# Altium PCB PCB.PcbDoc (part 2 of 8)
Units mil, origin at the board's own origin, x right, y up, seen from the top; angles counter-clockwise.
Board outline 11229.24 x 7764.43 mil, 14 copper layers (Top Layer, GND1, Signal 1, GND2, Signal 2, GND3, Singal 3, Power 1, GND4, Power 2, GND5, Power 3, GND6, Bottom Layer), stack 91.892 mil thick; 877 components, 305 nets, 2660 pads, 2851 vias.
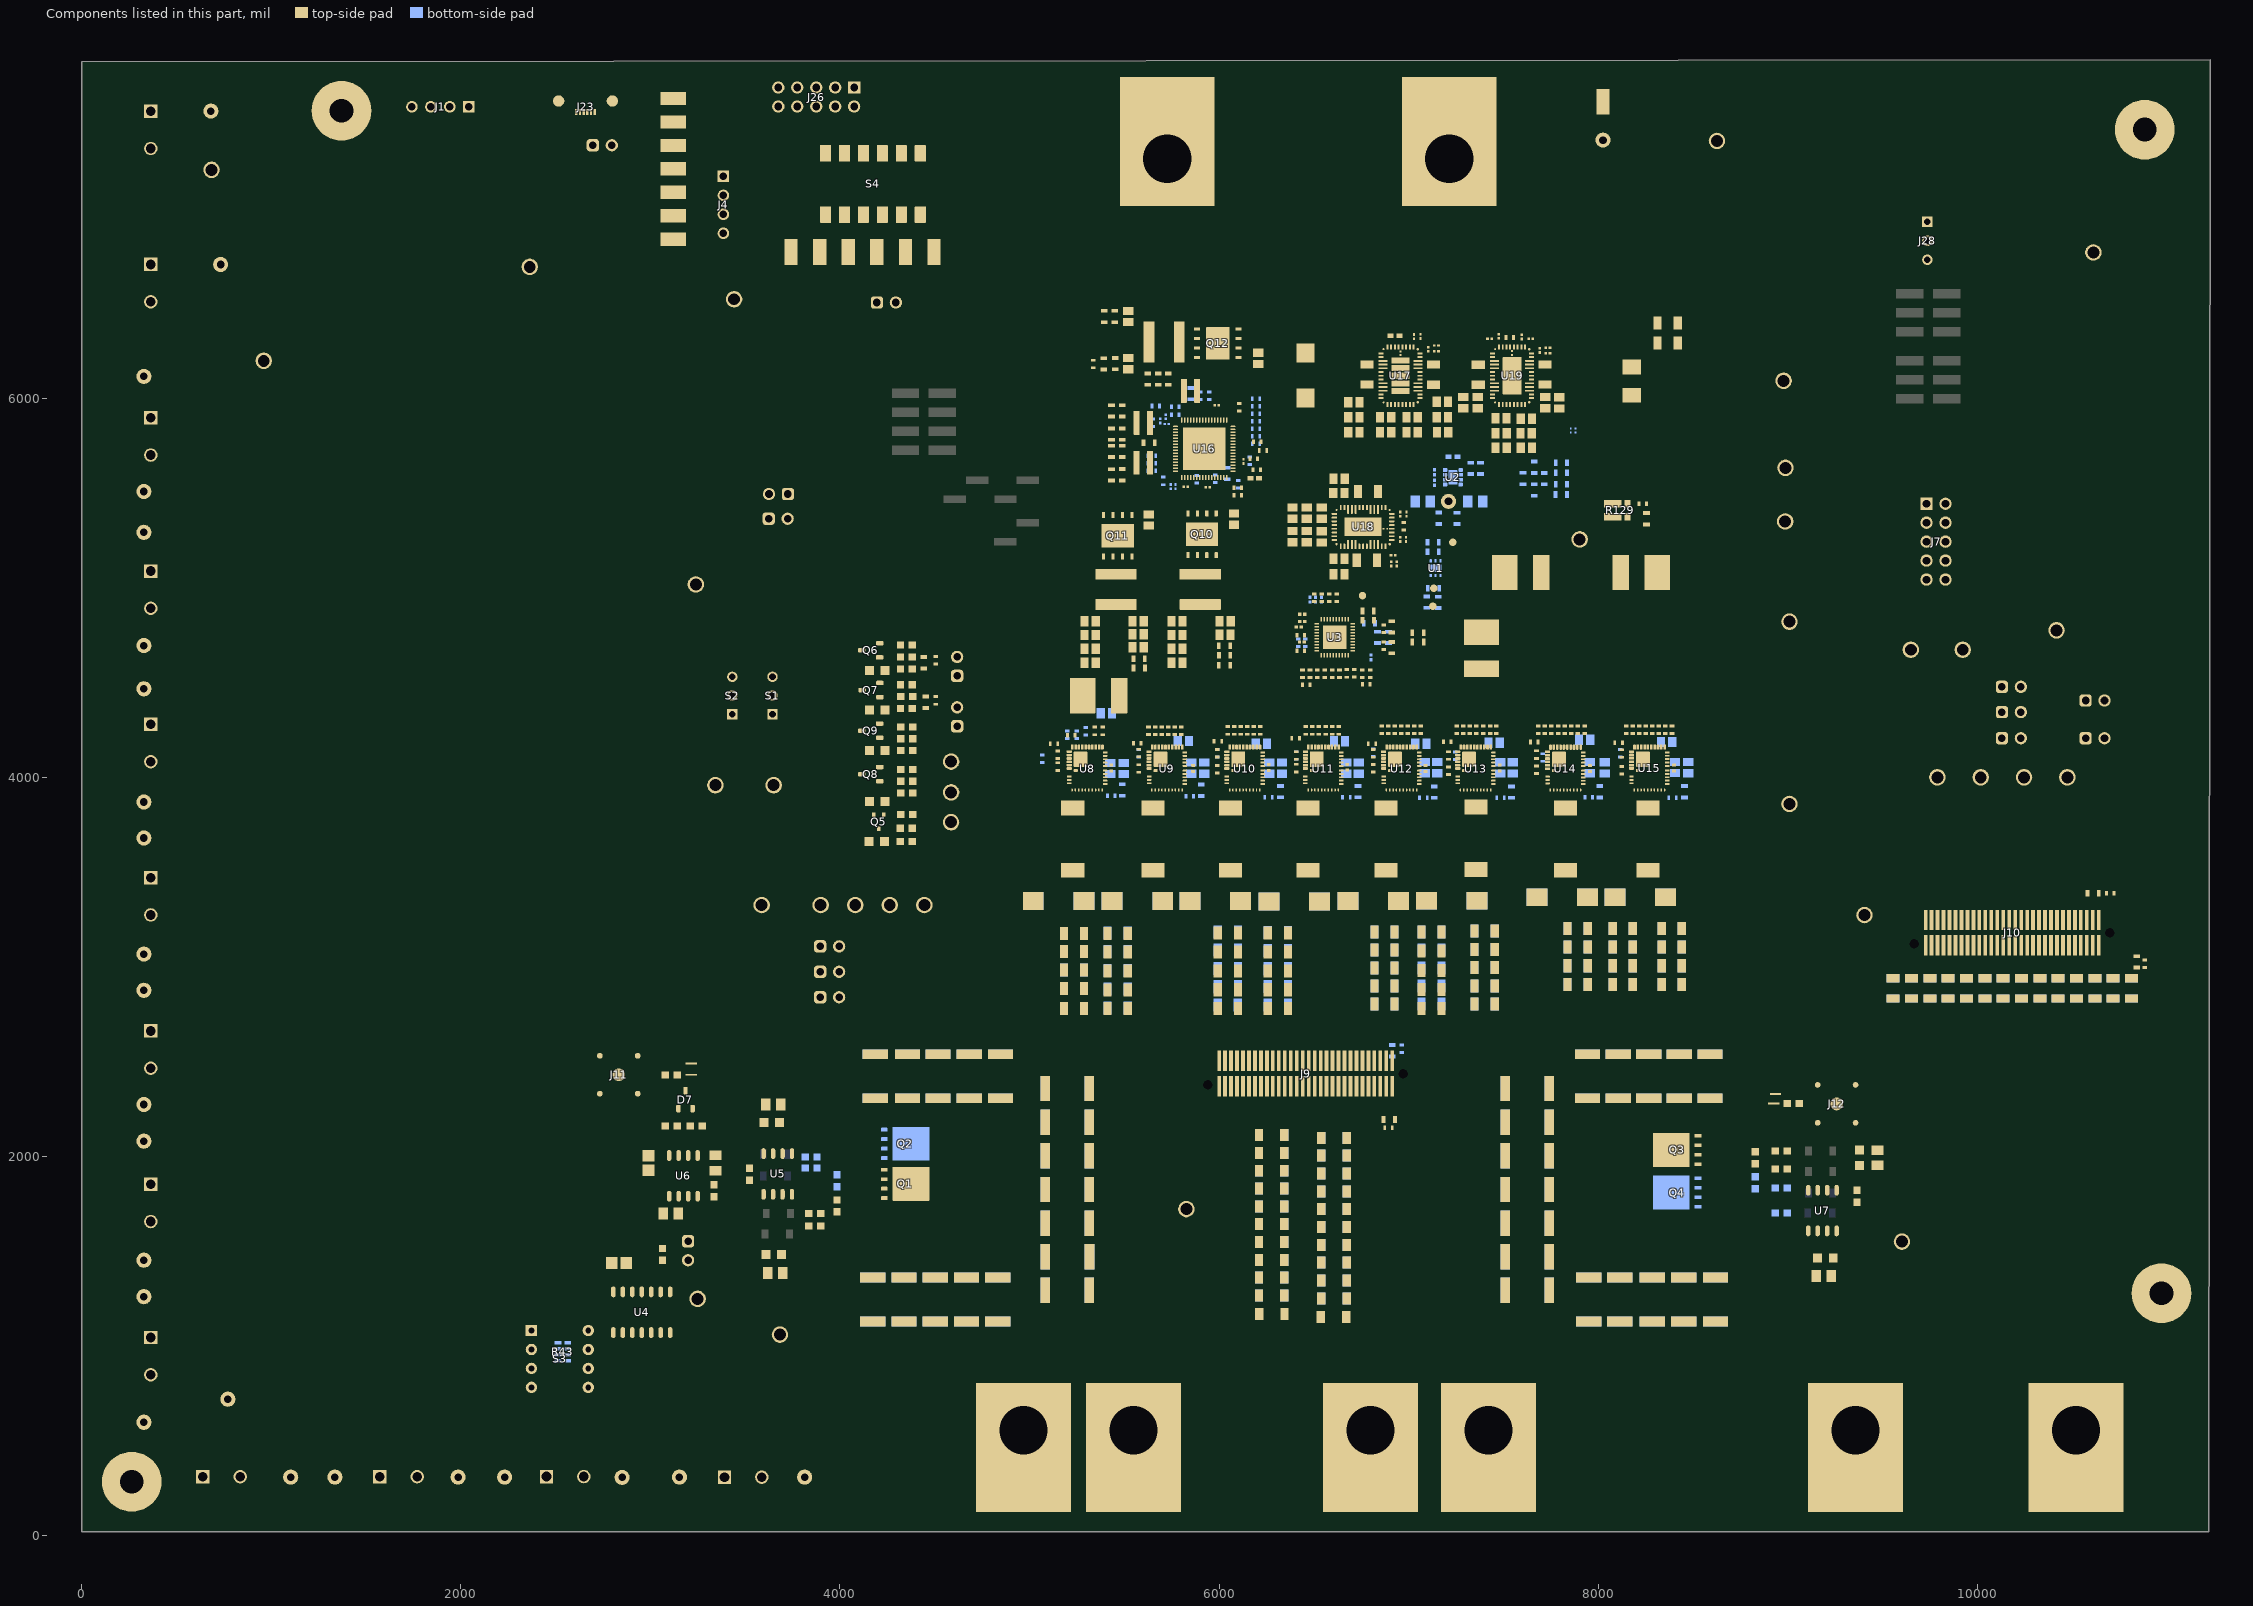
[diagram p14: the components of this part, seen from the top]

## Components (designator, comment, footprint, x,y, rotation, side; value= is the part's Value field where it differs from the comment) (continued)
J40 "TSW-102-07-G-S" TSW-102-07-G-S 10180,4477 r0 top
J41 "TSW-102-07-G-S" TSW-102-07-G-S 10180,4344 r0 top
J42 "TSW-102-07-G-S" TSW-102-07-G-S 10180,4205.9 r0 top
J43 "TSW-102-07-G-S" TSW-102-07-G-S 10621.2,4405.1 r0 top
J44 "TSW-102-07-G-S" TSW-102-07-G-S 10621.2,4205.9 r0 top
L1 "PA4059.550HLT" FP-PA4059.550HLT_SMT_IND_5MM5_5MM7-MFG 8177.1,6090.13 r270 top value=55nH
L2 "SLR1050A-151KEB" SLR1050 5228.42,3673.95 r270 top value=150nH
L3 "SLR1050A-151KEB" SLR1050 5651.54,3673.95 r270 top value=150nH
L4 "SLR1050A-151KEB" SLR1050 6061.26,3673.95 r270 top value=150nH
L5 "SLR1050A-151KEB" SLR1050 6470.18,3673.95 r270 top value=150nH
L6 "SLR1050A-151KEB" SLR1050 6880.87,3673.95 r270 top value=150nH
L7 "SLR1050A-151KEB" SLR1050 7355.5,3678.4 r270 top value=150nH
L8 "SLR1050A-151KEB" SLR1050 7827.39,3673.95 r270 top value=150nH
L9 "SLR1050A-151KEB" SLR1050 8262.09,3673.95 r270 top value=150nH
L10 "XEL6030-471MEB" XEL6030_320 5900.8,4991.17 r270 top value=470nH
L11 "XEL6030-471MEB" XEL6030_320 5456.32,4991.17 r270 top value=470nH
L12 "XEL6030-471MEB" XEL6030_320 5710.13,6296.76 r180 top value=470nH
L13 "XEL3530-501MEC" FP-XEL3530-501MEC_SMT_IND_3MM2_3MM5-MFG 5849.36,6038.36 r180 top
L14 "XEL3530-501MEC" FP-XEL3530-501MEC_SMT_IND_3MM2_3MM5-MFG 5600.97,5659.2 r180 top
L15 "XEL3530-501MEC" FP-XEL3530-501MEC_SMT_IND_3MM2_3MM5-MFG 5600.97,5869.4 r180 top
Logo1 "CE Mark" CE_Mark_5mm 1678.6,4168.8 r0 top
Logo2 "Texas Instruments" TI_Stacked_Overlay_Small 1882.7,4588.7 r0 top
Logo3 "FCC disclaimer" FCC_disclaimer 2144.7,4396.1 r0 top
Logo4 "WEEE logo" WEEE_Minimum 2036.82,4195.72 r0 top
NT1 "Net-Tie" Net-Tie_10mil 7855.14,5829.36 r270 bottom net-tie
NT2 "Net-Tie" Net-Tie_10mil 7881.1,5829.36 r270 bottom net-tie
NT3 "Net-Tie" Net-Tie_10milWide_30milLong 3215.02,2430.69 r180 top net-tie
NT4 "Net-Tie" Net-Tie_10milWide_30milLong 8925.61,2278.57 r0 top net-tie
NT5 "Net-Tie" Net-Tie_10milWide_30milLong 3215.02,2489.38 r180 top net-tie
NT6 "Net-Tie" Net-Tie_10milWide_30milLong 8935.8,2329.7 r0 top net-tie
NT7 "Net-Tie" Net-Tie6milsWide_20milsLong#1 6822.7,5859.51 r0 top net-tie
NT8 "Net-Tie" Net-Tie6milsWide_20milsLong#1 6053.81,5058.82 r270 top net-tie
NT9 "Net-Tie" Net-Tie6milsWide_20milsLong#2 5493.3,5367 r270 top net-tie
NT10 "Net-Tie" Net-Tie6milsWide_20milsLong#1 5295.9,4957.3 r270 top net-tie
NT11 "Net-Tie" Net-Tie6milsWide_20milsLong#1 6103.7,6131.5 r90 top net-tie
NT12 "Net-Tie" Net-Tie6milsWide_20milsLong#1 5717.57,6493.5 r180 top net-tie
NT13 "Net-Tie" Net-Tie6milsWide_20milsLong#1 5819.6,5994.97 r90 top net-tie
NT14 "Net-Tie" Net-Tie6milsWide_20milsLong#1 5562.4,5732.45 r180 top net-tie
NT15 "Net-Tie" Net-Tie6milsWide_20milsLong#1 5562.4,5792.5 r180 top net-tie
NT16 "Net-Tie" Net-Tie_10mil 6957.21,6237.02 r90 top net-tie
NT17 "Net-Tie" Net-Tie_10mil 6877.3,5310.89 r180 top net-tie
NT18 "Net-Tie" Net-Tie_10mil 7545.53,6238.47 r270 top net-tie
NT19 "Net-Tie" Net-Tie6milsWide_20milsLong#1 5937.93,5367 r270 top net-tie
Q1 "CSD17303Q5" DQH0008A#1 4344.24,1854.75 r0 top value=30V
Q2 "CSD17303Q5" DQH0008A#2 4344.24,2066.03 r0 bottom value=30V
Q3 "CSD17303Q5" DQH0008A#1 8416.65,2033.71 r180 top value=30V
Q4 "CSD17303Q5" DQH0008A#2 8416.65,1809.31 r180 bottom value=30V
Q5 "BSS223PWH6327" SOT-323 4204.38,3765.6 r270 top value=-20V
Q6 "BSS123" SOT-23 4162.63,4669.5 r180 top value=100V
Q7 "BSS123" SOT-23 4163.8,4460 r180 top value=100V
Q8 "BSS123" SOT-23 4162.67,4016.53 r180 top value=100V
Q9 "BSS123" SOT-23 4162.63,4245.95 r180 top value=100V
Q10 "CSD86360Q5D" DQY0008A 5910.18,5281.81 r270 top value=25V
Q11 "CSD86360Q5D" DQY0008A 5465.35,5274.01 r270 top value=25V
Q12 "CSD86360Q5D" DQY0008A 5993.26,6289.17 r180 top value=25V
R1 "RC0603FR-071RL" 0603S 7255.51,5366 r270 bottom value=1.00
R2 "RC0603FR-071RL" 0603S 7158.59,5366.17 r270 bottom value=1.00
R3 "RC0201FR-07523KL" 0201 7136.95,5553.61 r270 bottom value=523k
R4 "CRCW06030000Z0EA" 0603S 7328.7,5629.22 r270 bottom value=0
R5 "RC0603FR-071RL" 0603S 7156.93,4922.57 r270 bottom value=1.00
R6 "CRCW0201100KFKED" 0201 7136.95,5608.54 r270 bottom value=100k
R7 "CRCW04020000Z0ED" 0402S 6440.11,4546.38 r90 top value=0
R8 "CRCW06030000Z0EA" 0603S 6913.4,2557.4 r270 bottom value=0
R9 "CRCW04020000Z0ED" 0402S 6479.67,4546.38 r90 top value=0
R10 "CRCW06030000Z0EA" 0603S 10611.24,3387.33 r180 top value=0
R11 "CRCW04020000Z0ED" 0402S 6798.43,4546.38 r90 top value=0
R12 "CRCW04020000Z0ED" 0402S 6754.52,4546.38 r90 top value=0
R13 "CRCW060320K0FKEA" 0603S 6893.65,4737.98 r270 bottom value=20.0k
R14 "CRCW06031M30FKEA" 0603S 6836.07,4737.9 r270 bottom value=1.30Meg
R15 "CRCW06030000Z0EA" 0603S 6897.7,2194.33 r0 top value=0
R16 "CRCW06030000Z0EA" 0603S 10840.47,3026.33 r90 top value=0
R17 "CRCW06030000Z0EA" 0603S 6786.32,4877.05 r0 top value=0
R18 "CRCW040259K0FKED" 0402S 6417.31,4709.51 r90 bottom value=59.0k
R19 "CRCW040220K0JNED" 0402S 6454.62,4709.59 r90 bottom value=20k
R20 "CRCW04020000Z0ED" 0402S 6431.59,4667.4 r0 top value=0
R21 "CRCW04020000Z0ED" 0402S 6431.3,4748.7 r0 top value=0
R22 "CRCW06031K00JNEA" 0603S 4453.15,4395.6 r270 top value=1.0k
R23 "CRCW06031K00JNEA" 0603S 4442.9,4603.9 r270 top value=1.0k
R24 "CRCW06030000Z0EA" 0603S 7805.91,5658.39 r180 bottom value=0
R25 "CRCW06030000Z0EA" 0603S 7049.59,4763.14 r0 top value=0
R26 "CRCW06030000Z0EA" 0603S 7805.91,5605.71 r180 bottom value=0
R27 "CRCW06030000Z0EA" 0603S 7049.59,4713.53 r0 top value=0
R28 "CRCW06030000Z0EA" 0603S 7714.7,5575.4 r90 bottom value=0
R29 "CRCW06030000Z0EA" 0603S 7805.91,5545.7 r180 bottom value=0
R30 "RC0201JR-7D10KL" 0201 6508.29,4937.78 r90 bottom value=10k
R31 "RC0201JR-7D10KL" 0201 6438.6,4822.31 r180 top value=10k
R32 "RC0201JR-7D10KL" 0201 6540.67,4937.78 r90 bottom value=10k
R33 "CRCW0603121KFKEA" 0603S 6911.63,4793.14 r270 top value=121k
R34 "RC0201JR-7D10KL" 0201 6419.75,4793.38 r180 top value=10k
R35 "RC0201JR-7D10KL" 0201 6437.5,4714.2 r180 top value=10k
R36 "RC0201JR-7D10KL" 0201 6801.08,4631.96 r270 bottom value=10k
R37 "CRCW0603121KFKEA" 0603S 6911.89,4684.2 r90 top value=121k
R38 "CRCW06030000Z0EA" 0603S 7805.4,5491.9 r180 bottom value=0
R39 "CSRN2512FKR200" 2512 4186.6,2422.84 r90 top value=0.2
R40 "CSRN2512FKR200" 2512 4356.56,2422.84 r90 top value=0.2
R41 "CSRN2512FKR200" 2512 4172.95,1245.3 r270 bottom value=0.2
R42 "CSRN2512FKR200" 2512 4337.81,1245.3 r270 bottom value=0.2
R43 "TC164-JR-0710KL" TC164 2538.5,969.1 r180 bottom value=10k
R44 "CSRN2512FKR200" 2512 5198.84,2003.01 r0 top value=0.2
R45 "CSRN2512FKR200" 2512 5198.84,2180.51 r0 top value=0.2
R46 "CSRN2512FKR200" 2512 5198.84,2358 r0 top value=0.2
R47 "CSRN2512FKR200" 2512 5198.84,1825.52 r0 top value=0.2
R48 "CSRN2512FKR200" 2512 5198.84,1648.03 r0 top value=0.2
R49 "CSRN2512FKR200" 2512 5199.93,1470.53 r0 top value=0.2
R50 "CSRN2512FKR200" 2512 5198.84,1293.04 r0 top value=0.2
R51 "CSRN2512FKR200" 2512 4172.95,1245.3 r270 top value=0.2
R52 "CSRN2512FKR200" 2512 4337.81,1245.3 r270 top value=0.2
R53 "CSRN2512FKR200" 2512 4502.68,1245.3 r270 top value=0.2
R54 "CSRN2512FKR200" 2512 4667.54,1245.3 r270 top value=0.2
R55 "CSRN2512FKR200" 2512 4832.4,1245.3 r270 top value=0.2
R56 "CSRN2512FKR200" 2512 4847.12,2422.84 r90 top value=0.2
R57 "CSRN2512FKR200" 2512 4682.36,2422.84 r90 top value=0.2
R58 "CSRN2512FKR200" 2512 4517.49,2422.84 r90 top value=0.2
R59 "CSRN2512FKR200" 2512 4502.68,1245.3 r270 bottom value=0.2
R60 "CSRN2512FKR200" 2512 4186.6,2422.84 r90 bottom value=0.2
R61 "CSRN2512FKR200" 2512 4356.56,2422.84 r90 bottom value=0.2
R62 "CSRN2512FKR200" 2512 4517.49,2422.84 r90 bottom value=0.2
R63 "CSRN2512FKR200" 2512 4682.36,2422.84 r90 bottom value=0.2
R64 "CSRN2512FKR200" 2512 4847.12,2422.84 r90 bottom value=0.2
R65 "CSRN2512FKR200" 2512 5198.84,2358 r0 bottom value=0.2
R66 "CSRN2512FKR200" 2512 5198.84,2180.51 r0 bottom value=0.2
R67 "CSRN2512FKR200" 2512 5198.84,2003.02 r0 bottom value=0.2
R68 "CSRN2512FKR200" 2512 5198.84,1825.52 r0 bottom value=0.2
R69 "CSRN2512FKR200" 2512 5198.84,1648.03 r0 bottom value=0.2
R70 "CSRN2512FKR200" 2512 5199.93,1470.53 r0 bottom value=0.2
R71 "CSRN2512FKR200" 2512 5198.84,1293.04 r0 bottom value=0.2
R72 "CSRN2512FKR200" 2512 4832.4,1245.3 r270 bottom value=0.2
R73 "CSRN2512FKR200" 2512 4667.54,1245.3 r270 bottom value=0.2
R74 "CRCW060375R0FKEA" 0603 3866.21,1633 r0 top value=75.0
R75 "CRCW060375R0FKEA" 0603 3847.51,1996 r0 bottom value=75.0
R76 "CRCW0805330RJNEA" 0805_HV 3659.52,1384.14 r180 top value=330
R77 "CRCW0603100RFKEA" 0603 3866.21,1699.1 r0 top value=100
R78 "CRCW0603100RFKEA" 0603 3847.51,1937.82 r0 bottom value=100
R79 "CRCW060310K0JNEA" 0603 3984.32,1738.47 r270 top value=10k
R80 "CRCW060310K0JNEA" 0603 3984.32,1871.89 r90 bottom value=10k
R81 "CRCW0805330RJNEA" 0805_HV 3647.72,2272.73 r180 top value=330
R82 "CSRN2512FKR200" 2512 7625.53,1825.52 r180 bottom value=0.2
R83 "CSRN2512FKR200" 2512 7625.53,1293.04 r180 bottom value=0.2
R84 "CRCW06038K06FKEA" 0603 3110.7,2159.73 r180 top value=8.06k
R85 "CRCW060310K0JNEA" 0603 3334.72,1818.82 r90 top value=10k
R86 "CSRN2512FKR200" 2512 7943.44,2422.84 r90 top value=0.2
R87 "CSRN2512FKR200" 2512 8105.12,2422.84 r90 top value=0.2
R88 "CSRN2512FKR200" 2512 8266.8,2422.84 r90 top value=0.2
R89 "CSRN2512FKR200" 2512 8428.48,2422.84 r90 top value=0.2
R90 "CSRN2512FKR200" 2512 8590.17,2422.84 r90 top value=0.2
R91 "CSRN2512FKR200" 2512 7625.53,2180.51 r180 top value=0.2
R92 "CSRN2512FKR200" 2512 7625.53,1825.52 r180 top value=0.2
R93 "CSRN2512FKR200" 2512 7625.53,2003.01 r180 top value=0.2
R94 "CSRN2512FKR200" 2512 7949.94,1245.3 r270 top value=0.2
R95 "CSRN2512FKR200" 2512 8113.57,1245.3 r270 top value=0.2
R96 "CSRN2512FKR200" 2512 8284.59,1245.3 r270 top value=0.2
R97 "CSRN2512FKR200" 2512 8451.91,1245.3 r270 top value=0.2
R98 "CSRN2512FKR200" 2512 8619.24,1245.3 r270 top value=0.2
R99 "CSRN2512FKR200" 2512 7625.53,1648.03 r180 top value=0.2
R100 "CSRN2512FKR200" 2512 7625.53,1470.53 r180 top value=0.2
R101 "CSRN2512FKR200" 2512 8266.8,2422.84 r90 bottom value=0.2
R102 "CSRN2512FKR200" 2512 8428.48,2422.84 r90 bottom value=0.2
R103 "CSRN2512FKR200" 2512 8590.17,2422.84 r90 bottom value=0.2
R104 "CSRN2512FKR200" 2512 7625.53,2180.51 r180 bottom value=0.2
R105 "CSRN2512FKR200" 2512 7625.53,2003.01 r180 bottom value=0.2
R106 "CSRN2512FKR200" 2512 7625.53,2358 r180 bottom value=0.2
R107 "CSRN2512FKR200" 2512 8105.12,2422.84 r90 bottom value=0.2
R108 "CSRN2512FKR200" 2512 7943.44,2422.84 r90 bottom value=0.2
R109 "CSRN2512FKR200" 2512 8284.59,1245.3 r270 bottom value=0.2
R110 "CSRN2512FKR200" 2512 8451.91,1245.3 r270 bottom value=0.2
R111 "CSRN2512FKR200" 2512 8619.24,1245.3 r270 bottom value=0.2
R112 "CSRN2512FKR200" 2512 7625.53,1470.53 r180 bottom value=0.2
R113 "CSRN2512FKR200" 2512 7625.53,1648.03 r180 bottom value=0.2
R114 "CSRN2512FKR200" 2512 8113.57,1245.3 r270 bottom value=0.2
R115 "CSRN2512FKR200" 2512 7949.94,1245.3 r270 bottom value=0.2
R116 "CRCW06038K06FKEA" 0603 3063.33,1482.56 r270 top value=8.06k
R117 "CRCW0603100KFKEA" 0603 3241.68,2159.73 r180 top value=100k
R118 "CRCW060375R0FKEA" 0603 8966.67,2029.32 r180 top value=75.0
R119 "CRCW060375R0FKEA" 0603 8966.67,1832.39 r180 bottom value=75.0
R120 "CRCW0805330RJNEA" 0805_HV 9472.77,1992.24 r270 top value=330
R121 "CRCW0603100RFKEA" 0603 8966.67,1934.05 r180 top value=100
R122 "CRCW0603100RFKEA" 0603 8966.67,1701.29 r180 bottom value=100
R123 "CRCW060310K0JNEA" 0603 8828.88,1860.03 r270 bottom value=10k
R124 "CRCW060310K0JNEA" 0603 8828.88,1991.82 r90 top value=10k
R125 "CSRN2512FKR200" 2512 7625.53,2358 r180 top value=0.2
R126 "CSRN2512FKR200" 2512 7625.53,1293.04 r180 top value=0.2
R127 "CRCW0805330RJNEA" 0805_HV 9190.82,1369.87 r180 top value=330
R128 "CRCW040210R0FKED" 0402S 8234.9,5442.9 r180 top value=10.0
R129 "RL1632L4-0R5M-FNH" RL1632L4 8100.91,5408.59 r270 top value=0.0005
R130 "CRCW0603180RJNEA" 0603 4350.92,4570.36 r0 top value=180
R131 "CRCW0603180RJNEA" 0603 4350.9,4363.1 r0 top value=180
R132 "CRCW0603180RJNEA" 0603 4351.85,4140.35 r0 top value=180
R133 "CRCW060310K0JNEA" 0603 4351.85,4203.06 r180 top value=10k
R134 "CRCW0603180RJNEA" 0603 4351.89,3916.76 r0 top value=180
R135 "CRCW060310K0JNEA" 0603 4351.89,3979.13 r180 top value=10k
R136 "CRCW060310K0JNEA" 0603 4350.68,3730.86 r180 top value=10k
R137 "CRCW060310K0JNEA" 0603 4350.9,4634.2 r180 top value=10k
R138 "CRCW060310K0JNEA" 0603 4352.72,4425.9 r180 top value=10k
R139 "CRCW06030000Z0EA" 0603 4351.89,3802.81 r0 top value=0
R140 "CRCW06030000Z0EA" 0603 4351.89,4041.36 r0 top value=0
R141 "CRCW06030000Z0EA" 0603 4350.9,4697.9 r0 top value=0
R142 "CRCW06030000Z0EA" 0603 4350.9,4487.96 r0 top value=0
R143 "CRCW06030000Z0EA" 0603 4351.85,4265.65 r0 top value=0
R144 "CRCW0603180RJNEA" 0603 4350.68,3661.08 r180 top value=180
R145 "CRCW06030000Z0EA" 0603 3110.5,2430.2 r180 top value=0
R146 "CRCW06030000Z0EA" 0603 9029.1,2279.8 r0 top value=0
R147 "CRCW06031R00JNEA" 0603S 5488.63,3932.65 r270 bottom value=1.0
R148 "CRCW04020000Z0ED" 0402S 5297.36,4243.12 r90 bottom value=0
R149 "ERA-2AEB1022X" 0402S 5219.62,4222.4 r0 top value=10.2k
R150 "CRCW04020000Z0ED" 0402S 6502.99,4946.58 r270 top value=0
R151 "CRCW04020000Z0ED" 0402S 6518.95,4546.2 r90 top value=0
R152 "CRCW04022R20JNED" 0402S 5068.1,4098.26 r270 bottom value=2.2
R153 "CRCW04020000Z0ED" 0402S 5248.68,4224.65 r270 bottom value=0
R154 "CRCW04020000Z0ED" 0402S 5387.38,4244.47 r90 top value=0
R155 "CRCW06031R00JNEA" 0603S 5906.69,3931.84 r270 bottom value=1.0
R156 "CRCW04020000Z0ED" 0402S 5731.89,4245.93 r90 top value=0
R157 "ERA-2AEB1022X" 0402S 5627.84,4245.37 r270 top value=10.2k
R158 "CRCW04020000Z0ED" 0402S 6542.56,4946.58 r270 top value=0
R159 "CRCW04022R20JNED" 0402S 5576.28,4127.15 r270 bottom value=2.2
R160 "CRCW04020000Z0ED" 0402S 6557.75,4546.1 r90 top value=0
R161 "CRCW04020000Z0ED" 0402S 5697.21,4245.93 r270 top value=0
R162 "CRCW04020000Z0ED" 0402S 5801.25,4245.93 r90 top value=0
R163 "CRCW06031R00JNEA" 0603S 6324.2,3924.19 r270 bottom value=1.0
R164 "CRCW04020000Z0ED" 0402S 6147.74,4247.16 r90 top value=0
R165 "ERA-2AEB1022X" 0402S 6044.96,4247.02 r270 top value=10.2k
R166 "CRCW04020000Z0ED" 0402S 6582.12,4946.58 r270 top value=0
R167 "CRCW04022R20JNED" 0402S 5990.4,4126.16 r270 bottom value=2.2
R168 "CRCW04020000Z0ED" 0402S 6596.75,4546.5 r90 top value=0
R169 "CRCW04020000Z0ED" 0402S 6079.22,4247.16 r270 top value=0
R170 "CRCW04020000Z0ED" 0402S 6216.26,4247.16 r90 top value=0
R171 "CRCW06031R00JNEA" 0603S 6733.08,3924.19 r270 bottom value=1.0
R172 "CRCW04020000Z0ED" 0402S 6561.72,4247.16 r90 top value=0
R173 "ERA-2AEB1022X" 0402S 6457.86,4247.02 r270 top value=10.2k
R174 "CRCW04020000Z0ED" 0402S 6621.69,4946.58 r270 top value=0
R175 "CRCW04020000Z0ED" 0402S 6635.35,4546.8 r90 top value=0
R176 "CRCW04022R20JNED" 0402S 6407.63,4115.03 r270 bottom value=2.2
R177 "CRCW04020000Z0ED" 0402S 6492.48,4247.16 r270 top value=0
R178 "CRCW04020000Z0ED" 0402S 6630.96,4247.16 r90 top value=0
R179 "CRCW06031R00JNEA" 0603S 7136.11,3921.87 r270 bottom value=1.0
R180 "CRCW04020000Z0ED" 0402S 6961.99,4250.49 r90 top value=0
R181 "ERA-2AEB1022X" 0402S 6858.99,4250.67 r270 top value=10.2k
R182 "CRCW04020000Z0ED" 0402S 6996.32,4250.49 r90 top value=0
R183 "CRCW04022R20JNED" 0402S 6813.95,4130.15 r270 bottom value=2.2
R184 "CRCW04020000Z0ED" 0402S 6674.05,4548 r90 top value=0
R185 "CRCW04020000Z0ED" 0402S 6927.65,4250.49 r270 top value=0
R186 "CRCW04020000Z0ED" 0402S 7064.99,4250.49 r90 top value=0
R187 "CRCW06031R00JNEA" 0603S 7543.17,3921.41 r270 bottom value=1.0
R188 "CRCW04020000Z0ED" 0402S 7358.02,4250.49 r90 top value=0
R189 "ERA-2AEB1022X" 0402S 7253.3,4250.1 r270 top value=10.2k
R190 "CRCW04020000Z0ED" 0402S 7392.92,4250.49 r90 top value=0
R191 "CRCW04022R20JNED" 0402S 7246.84,4112.91 r270 bottom value=2.2
R192 "CRCW04020000Z0ED" 0402S 6714.15,4548.3 r90 top value=0
R193 "CRCW04020000Z0ED" 0402S 7323.11,4250.49 r270 top value=0
R194 "CRCW04020000Z0ED" 0402S 7462.73,4250.49 r90 top value=0
R195 "CRCW06031R00JNEA" 0603S 8007.93,3923.8 r270 bottom value=1.0
R196 "CRCW04020000Z0ED" 0402S 7823.35,4250.1 r90 top value=0
R197 "ERA-2AEB1022X" 0402S 7718.49,4250.1 r270 top value=10.2k
R198 "CRCW04020000Z0ED" 0402S 7858.3,4250.1 r90 top value=0
R199 "CRCW04020000Z0ED" 0402S 7683.54,4250.1 r90 top value=0
R200 "CRCW04022R20JNED" 0402S 7706.6,4104.17 r270 bottom value=2.2
R201 "CRCW04020000Z0ED" 0402S 7753.45,4250.1 r270 top value=0
R202 "CRCW04020000Z0ED" 0402S 7928.21,4250.76 r90 top value=0
R203 "CRCW06031R00JNEA" 0603S 8455.5,3923.3 r270 bottom value=1.0
R204 "CRCW04020000Z0ED" 0402S 8285.77,4250.1 r90 top value=0
R205 "ERA-2AEB1022X" 0402S 8182.04,4250.1 r270 top value=10.2k
R206 "CRCW04020000Z0ED" 0402S 8320.35,4250.1 r90 top value=0
R207 "CRCW04022R20JNED" 0402S 8115.4,4126.3 r270 bottom value=2.2
R208 "CRCW04020000Z0ED" 0402S 8147.46,4250.1 r90 top value=0
R209 "CRCW04020000Z0ED" 0402S 8251.2,4250.1 r270 top value=0
R210 "CRCW04020000Z0ED" 0402S 8389.51,4250.1 r90 top value=0
R211 "CRCW040212K4FKED" 0402S 5979.8,5574.2 r90 bottom value=12.4k
R212 "CRCW040212K4FKED" 0402S 5704.7,5563.21 r270 bottom value=12.4k
R213 "CRCW040212K4FKED" 0402S 6105.63,5951.4 r90 top value=12.4k
R214 "CRCW04020000Z0ED" 0402S 5651.14,5870.65 r90 bottom value=0
R215 "CRCW0402100KJNED" 0402S 6194.8,5996.47 r0 bottom value=100k
R216 "CRCW0402100KJNED" 0402S 5768.84,5912.95 r180 bottom value=100k
R217 "CRCW0402100KJNED" 0402S 6194.8,5917.48 r0 bottom value=100k
R218 "CRCW0402100KJNED" 0402S 6194.8,5877.99 r0 bottom value=100k
R219 "CRCW0402100KJNED" 0402S 6194.8,5838.49 r0 bottom value=100k
R220 "CRCW0402100KJNED" 0402S 5768.83,5955.23 r180 bottom value=100k
R221 "CRCW0402100KJNED" 0402S 6194.8,5956.98 r180 bottom value=100k
R222 "CRCW0402100KJNED" 0402S 5645.69,5656.6 r0 bottom value=100k
R223 "CRCW0402100KJNED" 0402S 5665.99,5958.66 r180 bottom value=100k
R224 "CRCW0402100KJNED" 0402S 5645.69,5696.61 r0 bottom value=100k
R225 "CRCW0402100KJNED" 0402S 5645.69,5616.59 r0 bottom value=100k
R226 "CRCW04021K00JNED" 0402S 6194.8,5759.5 r0 bottom value=1.0k
R227 "CRCW04021K00JNED" 0402S 6194.8,5799 r0 bottom value=1.0k
R228 "RC0201FR-0791KL" 0201L#1 7063,6325.79 r90 top value=91.0k
R229 "RC0201FR-0710K2L" 0201L#1 7028.2,6324.79 r90 top value=10.2k
R230 "RC0201FR-7D10KL" 0201L#2 7103.85,6258.34 r90 top value=10.0k
R231 "RC0201FR-0710K7L" 0201L#3 7146.76,6245.94 r0 top value=10.7k
R232 "RC0201FR-0753K6L" 0201L#1 7146.76,6277.53 r0 top value=53.6k
R233 "CRCW020156K0FKED" 0201L#1 6956.9,5254.38 r270 top value=56.0k
R234 "CRCW020110K0FKED" 0201L#1 6986.22,5254.38 r270 top value=10.0k
R235 "RC0201FR-7D10KL" 0201L#1 6918.57,5171.77 r180 top value=10.0k
R236 "CRCW02019K09FKED" 0201L#1 6956.9,5387.98 r90 top value=9.09k
R237 "RC0201FR-0715K4L" 0201L#1 6907.55,5125.12 r270 top value=15.4k
R238 "RC0201FR-0717K4L" 0201L#1 6938.26,5125.12 r270 top value=17.4k
R239 "CRCW020110K0FKED" 0201L#1 6988.74,5387.98 r270 top value=10.0k
R240 "RC0201FR-0726K1L" 0201L#1 7644.41,6314.24 r0 top value=26.1k
R241 "CRCW020110K0FKED" 0201L#1 7596.71,6323.34 r90 top value=10.0k
R242 "RC0201FR-7D10KL" 0201L#1 7692.29,6252.38 r270 top value=10.0k
R243 "RC0201FR-0714KL" 0201L#1 7426.91,6314.14 r180 top value=14.0k
R244 "RC0201FR-0715K4L" 0201L#1 7735.2,6236.77 r0 top value=15.4k
R245 "RC0201FR-0717K4L" 0201L#1 7735.2,6265.16 r0 top value=17.4k
R246 "CRCW020110K0FKED" 0201L#1 7475.81,6326.34 r270 top value=10.0k
S1 "EG1218" SW_EG1218 3644.2,4431.13 r90 top
S2 "EG1218" SW_EG1218 3432.2,4431.13 r90 top
S3 "78B04ST" SW_78B04ST 2522.4,931.3 r0 top
S4 "SDA06H1SBD" SW_SDA06H1SBD 4174.11,7129.8 r0 top
T1 "CB70-14-CY" CB70-14-CY 7214.7,7263.1 r270 top
T2 "CB70-14-CY" CB70-14-CY 5727.1,7263.1 r270 top
T3 "CB70-14-CY" CB70-14-CY 7421.9,555.2 r90 top
T4 "CB70-14-CY" CB70-14-CY 6799,555.2 r90 top
T5 "CB70-14-CY" CB70-14-CY 4968.43,555.2 r90 top
T6 "CB70-14-CY" CB70-14-CY 5549.14,555.2 r90 top
T7 "CB70-14-CY" CB70-14-CY 10520.5,555.2 r90 top
T8 "CB70-14-CY" CB70-14-CY 9356.9,555.2 r90 top
TP1 "5000" Keystone5000#1 327.8,5507.5 r90 top
TP2 "TP_SM_1MM" TP_SM_1MM 7232.96,5239.78 r0 top
TP3 "TP_SM_1MM" TP_SM_1MM 7133.05,4997.2 r0 top
TP4 "5000" Keystone5000#1 7210.37,5455.65 r0 top
TP5 "5001" Keystone5001 327.8,6115 r90 top
TP6 "TP_SM_1MM" TP_SM_1MM 7128.13,4902.33 r0 top
TP7 "PGND" Keystone5006 8978.2,6091.6 r0 top
TP8 "TP_SM_1MM" TP_SM_1MM 6756.8,4957.8 r0 top
TP9 "EN_VOUT_A" Keystone5007 3650.3,3958.07 r180 top
TP10 "EN_VOUT_B" Keystone5007 3342.95,3958.07 r180 top
TP11 "TSENA" Keystone5007 9923.48,4672.8 r180 top
TP12 "TSENB" Keystone5007 9649.4,4672.8 r180 top
TP13 "DL_CLK1" Keystone5007 3249.16,1248.3 r0 top
TP14 "IIN_CSP1" Keystone5007 8988.2,5632.1 r0 top
TP15 "5007" Keystone5007 8986.5,5349.4 r0 top
TP16 "VINC1" Keystone5005 7902.55,5254.82 r0 top
TP17 "PGND" Keystone5006 8626.7,7357 r0 top
TP18 "PGND" Keystone5006 3441.5,6521.9 r0 top
TP19 "PVOUT_A" Keystone5005 5827.8,1722 r0 top
TP20 "PVOUT_B" Keystone5005 9404.94,3273.03 r90 top
TP21 "GND" Keystone5006 9009.2,4820.78 r180 top
TP22 "GND" Keystone5006 684.9,7204.3 r180 top
TP23 "GND" Keystone5006 9009.2,3859 r0 top
TP24 "GND" Keystone5006 3587,3325.8 r180 top
TP25 "GND" Keystone5006 960.2,6197 r270 top
TP26 "GND" Keystone5006 9602.6,1550.51 r180 top
TP27 "GND" Keystone5006 10418.1,4775.2 r180 top
TP28 "VR-FAULT" Keystone5007 4586.16,3763.04 r0 top
TP29 "VOUT_A_RDY" Keystone5007 4586.47,4082.8 r180 top
TP30 "VOUT_B_RDY" Keystone5007 4586.47,3920.2 r180 top
TP31 "PWM1" Keystone5007 4445,3325.8 r180 top
TP33 "PWM2" Keystone5007 4262.87,3325.8 r180 top
TP35 "PWM3" Keystone5007 4080.74,3325.8 r180 top
TP37 "PWM4" Keystone5007 3898.6,3325.8 r180 top
TP39 "PWM5" Keystone5007 9789.76,3999.8 r180 top
TP41 "PWM6" Keystone5007 10018.24,3999.8 r0 top
TP43 "BPWM2" Keystone5007 10246.72,3999.8 r0 top
TP45 "BPWM1" Keystone5007 10475.2,3999.8 r0 top
TP47 "5000" Keystone5000#2 2850.9,307.7 r180 top
TP48 "5001" Keystone5001 2231,307.7 r180 top
TP49 "5000" Keystone5000#1 3813.9,307.7 r180 top
TP50 "5001" Keystone5001 3153.3,307.7 r180 top
TP51 "5000" Keystone5000#1 327.8,1452.2 r90 top
TP52 "5001" Keystone5001 327.8,2080.2 r90 top
TP53 "5000" Keystone5000#1 327.8,597.3 r90 top
TP54 "5001" Keystone5001 327.8,1259.9 r90 top
TP55 "5000" Keystone5000#1 1985.6,307.7 r180 top
TP56 "5001" Keystone5001 1335.7,307.7 r180 top
TP57 "5000" Keystone5000#1 1102.4,307.7 r0 top
TP58 "5001" Keystone5001 770.9,719 r180 top
TP59 "5015" Testpoint_Keystone_Miniature 8025.4,7564.18 r270 top
TP60 "5000" Keystone5000#1 8025.4,7361.4 r270 top
TP61 "5015" Testpoint_Keystone_Miniature 4043.92,6771.17 r90 top
TP62 "5015" Testpoint_Keystone_Miniature 3892.99,6771.17 r90 top
TP63 "5015" Testpoint_Keystone_Miniature 3742.07,6771.17 r90 top
TP64 "5015" Testpoint_Keystone_Miniature 4345.76,6771.17 r90 top
TP65 "5015" Testpoint_Keystone_Miniature 4194.84,6771.17 r90 top
TP66 "5015" Testpoint_Keystone_Miniature 4496.68,6771.17 r90 top
TP67 "5000" Keystone5000#1 327.8,2273.8 r90 top
TP68 "5001" Keystone5001 327.8,2876.2 r90 top
TP69 "5000" Keystone5000#1 327.8,3067.1 r90 top
TP70 "5015" Testpoint_Keystone_Miniature 3120.11,7333.46 r180 top
TP71 "5000" Keystone5000#1 732.75,6705.32 r90 top
TP72 "5015" Testpoint_Keystone_Miniature 3120.11,6961.72 r180 top
TP73 "5015" Testpoint_Keystone_Miniature 3120.11,7209.55 r180 top
TP74 "5000" Keystone5000#1 681.3,7514.2 r90 top
TP75 "5015" Testpoint_Keystone_Miniature 3120.11,7085.63 r180 top
TP76 "5015" Testpoint_Keystone_Miniature 3120.11,6838.8 r0 top
TP77 "5001" Keystone5001 327.8,3679.8 r90 top
TP78 "5015" Testpoint_Keystone_Miniature 3120.11,7581.3 r180 top
TP79 "5015" Testpoint_Keystone_Miniature 3120.11,7457.38 r180 top
TP80 "5000" Keystone5000#1 327.8,4694.9 r270 top
TP81 "5001" Keystone5001 327.8,5292.2 r90 top
TP82 "5000" Keystone5000#1 327.8,3869.5 r270 top
TP83 "5001" Keystone5001 327.8,4466.8 r270 top
TP84 "GND" Keystone5006 3683.49,1059.81 r0 top
TP85 "GND" Keystone5006 3239.9,5017.3 r0 top
TP86 "GND" Keystone5006 2363.7,6692.4 r0 top
TP87 "GND" Keystone5006 10612.7,6768.5 r0 top
U1 "TLV76733DRVT" DRV0006A-MFG 7142.4,5103.08 r90 bottom
U2 "TPS82130SILR" SIL0008D_SMD 7233.49,5582.6 r180 bottom
U3 "TPS53688RSB" RSB0040E 6610.14,4738.26 r270 top
U4 "CD74HCT08M" D0014A_N 2954.4,1177.8 r90 top
U5 "UCC27324DR" D0008A_N 3672.04,1907.32 r270 top
U6 "TLC555CD" D0008A_N 3174.16,1897.38 r90 top
U7 "UCC27324DR" D0008A_N 9183.21,1714.36 r90 top
U8 "CSD95410RWJ" RWJ0041A 5304.16,4045.11 r0 top
U9 "CSD95410RWJ" RWJ0041A 5725.4,4045.11 r0 top
U10 "CSD95410RWJ" RWJ0041A 6135.55,4045.11 r0 top
U11 "CSD95410RWJ" RWJ0041A 6549.95,4045.11 r0 top
U12 "CSD95410RWJ" RWJ0041A 6962.61,4045.11 r0 top
U13 "CSD95410RWJ" RWJ0041A 7353.3,4045.11 r0 top
U14 "CSD95410RWJ" RWJ0041A 7827.39,4044.72 r0 top
U15 "CSD95410RWJ" RWJ0041A 8270.41,4045.43 r0 top
U16 "TPS65086100RSKT" RSK0064C 5921.79,5732.45 r270 top
U17 "TPSM5D1806RDB" RDB0051A-MFG#1 6957.19,6118.09 r0 top
U18 "TPSM5D1806RDB" RDB0051A-MFG#2 6759.86,5320.73 r270 top
U19 "TPSM5D1806RDB" RDB0051A-MFG#2 7545.64,6118.09 r0 top

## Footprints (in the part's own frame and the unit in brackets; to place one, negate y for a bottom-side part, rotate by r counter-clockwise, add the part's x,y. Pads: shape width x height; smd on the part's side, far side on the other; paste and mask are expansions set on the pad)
0201 [mm] "Data from Kemet datasheet CC101_COM dated 7/28/11"
  rect 0.46x0.42 smd mask+0.048: 1(-0.33,0) 2(0.33,0)
  body extent -0.31,-0.16 0.31,0.16, height 0.26
0201_033L [mm] "0201"
  rect 0.36x0.32 smd mask+0.048: 1(-0.28,0) 2(0.28,0)
  body extent -0.31,-0.16 0.31,0.16, height 0.33
0201L#1 [mm] "Data from Kemet datasheet CC101_COM dated 7/28/11"
  rect 0.36x0.32 smd mask+0.048: 1(-0.28,0) 2(0.28,0)
  body extent -0.31,-0.16 0.31,0.16, height 0.26
0201L#2 [mm] "Data from Kemet datasheet CC101_COM dated 7/28/11"
  rect 0.36x0.32 smd mask+0.048: 1(-0.28,-0.003) 2(0.28,-0.003)
  body extent -0.31,-0.16 0.31,0.16, height 0.26
0201L#3 [mm] "Data from Kemet datasheet CC101_COM dated 7/28/11"
  rect 0.36x0.32 smd mask+0.048: 1(-0.28,0.02) 2(0.28,0.02)
  body extent -0.31,-0.16 0.31,0.16, height 0.26
0402 [mm] "0402 from SM-752 data"
  rect 0.8x0.6 smd: 1(-0.6,0) 2(0.6,0)
  silkscreen extent -1.22,-0.52 1.22,0.52, body extent -0.55,-0.3 0.55,0.3, height 0.6
0402_065 [mm] "0402"
  rect 0.8x0.6 smd: 1(-0.6,0) 2(0.6,0)
  silkscreen extent -1.22,-0.52 1.22,0.52, body extent -0.55,-0.3 0.55,0.3, height 0.65
0402_065S [mil] "Based on C0402S footprint from PADS legacy"
  rect 15x24 smd: 1(-20,0) 2(20,0)
  body extent -22,-12 22,12, height 26
0402S [mil] "Based on C0402S footprint from PADS legacy"
  rect 15x24 smd: 1(-20,0) 2(20,0)
  body extent -22,-12 22,12, height 24
0603 [mm] "0603 from SM-752 data"
  rect 1x0.95 smd: 1(-0.8,0) 2(0.8,0)
  silkscreen extent -1.52,-0.69 1.52,0.69, body extent -0.87,-0.47 0.87,0.47, height 1
0603S [mil]
  rect 20x35 smd: 1(-30,0) 2(30,0)
  body extent -34,-19 34,19, height 39
0805_HV [mil] "0805 with 30mil clearance between pads"
  rect 50x63 smd: 1(-40,0) 2(40,0)
  silkscreen extent -74,-40 74,40, body extent -43,-29 43,29, height 57
0805L [mm] "0805 from SM-752 data"
  rect 1.1x1.4 smd: 1(-0.75,0) 2(0.75,0)
  body extent -1.1,-0.72 1.1,0.72, height 1.45
0805M [mm] "0805 from SM-752 data"
  rect 1.55x1.6 smd: 1(-0.975,0) 2(0.975,0)
  silkscreen extent -2.07,-1.12 2.07,1.12, body extent -1.1,-0.72 1.1,0.72, height 1.45
1206_180L [mm] "1206_180"
  rect 1.1x1.75 smd: 1(-1.35,0) 2(1.35,0)
  silkscreen extent -0.4,-0.77 0.4,0.77, body extent -1.75,-0.95 1.75,0.95, height 1.8
1206_190 [mm] "1206_190"
  rect 1.1x1.6 smd: 1(-1.7,0) 2(1.7,0)
  silkscreen extent -0.9,-1 0.9,1, body extent -1.75,-0.95 1.75,0.95, height 1.9
1206_190L [mm] "1206_190"
  rect 1.1x1.75 smd: 1(-1.35,0) 2(1.35,0)
  silkscreen extent -0.4,-0.77 0.4,0.77, body extent -1.75,-0.95 1.75,0.95, height 1.9
1206L [mm] "1206 from SM-752 data"
  rect 1.1x1.75 smd: 1(-1.35,0) 2(1.35,0)
  silkscreen extent -0.4,-0.77 0.4,0.77, body extent -1.7,-0.9 1.7,0.9, height 1.35
2512 [mm] "Chip Resistor, Body 6.3x3.2mm, IPC Medium Density"
  rect 1.3x3.4 smd: 1(-2.95,0) 2(2.95,0)
  silkscreen extent -1.9,-1.6 1.9,1.6, body extent -3.22,-1.67 3.22,1.67, height 0.71
7343-43 [mm] "Medium density IPC based on Kemet T495 series"
  rect 2.55x2.45 smd: 1(-3.025,0) 2(3.025,0)
  silkscreen extent -4.56,-2.3 3.8,2.3, body extent -3.8,-2.3 3.8,2.3, height 4.3
CB70-14-CY [mil] "Terminal 90A Lug"
  rect 680x500 hole 254 copper offset -90,0 paste-250: 1(0,0)
  body extent -1300,-260 250,260, height 714
CE_Mark_5mm [mil] "Minimum text height for CE Mark"
  silkscreen extent -138,-98 138,98
CONN_2510-6002 [mm] "3M 2500 series TS-0770-L December 15, 2011"
  rect 1.65x1.65 hole 1.016 mask+0: 1(-5.08,-1.27)
  round 1.65 hole 1.016 mask+0: 2(-5.08,1.27) 3(-2.54,-1.27) 4(-2.54,1.27) 5(0,-1.27) 6(0,1.27) 7(2.54,-1.27) 8(2.54,1.27) 9(5.08,-1.27) 10(5.08,1.27)
  silkscreen extent -10.01,-4.17 10.01,4.47, body extent -10.01,-4.11 10.01,4.52, height 9.92
CONN_5103308-1 [mm] "TE Connectivity (AMP) Rev E datasheet"
  rect 1.65x1.65 hole 1.016 mask+0: 1(-5.08,-1.27)
  round 1.65 hole 1.016 mask+0: 2(-5.08,1.27) 3(-2.54,-1.27) 4(-2.54,1.27) 5(0,-1.27) 6(0,1.27) 7(2.54,-1.27) 8(2.54,1.27) 9(5.08,-1.27) 10(5.08,1.27)
  silkscreen extent -10.16,-5.33 10.16,4.57, body extent -10.16,-4.57 10.16,4.57, height 9.87
controlCARD-180HSEC-60pinAddon [mm] "Pads are not numbered according to datasheet."
  round 0.025 hole 1.27 unplated mask+0.876: 61(-13.1,0) 62(13.1,1.5)
  rect 0.5x2.724 smd: 121(-11.6,-1.7) 122(-11.6,1.7) 123(-10.8,-1.7) 124(-10.8,1.7) 125(-10,-1.7) 126(-10,1.7) 127(-9.2,-1.7) 128(-9.2,1.7) 129(-8.4,-1.7) 130(-8.4,1.7) 131(-7.6,-1.7) 132(-7.6,1.7) 133(-6.8,-1.7) 134(-6.8,1.7) 135(-6,-1.7) 136(-6,1.7) 137(-5.2,-1.7) 138(-5.2,1.7) 139(-4.4,-1.7) 140(-4.4,1.7) 141(-3.6,-1.7) 142(-3.6,1.7) 143(-2.8,-1.7) 144(-2.8,1.7) 145(-2,-1.7) 146(-2,1.7) 147(-1.2,-1.7) 148(-1.2,1.7) 149(-0.4,-1.7) 150(-0.4,1.7) 151(0.4,-1.7) 152(0.4,1.7) 153(1.2,-1.7) 154(1.2,1.7) 155(2,-1.7) 156(2,1.7) 157(2.8,-1.7) 158(2.8,1.7) 159(3.6,-1.7) 160(3.6,1.7) 161(4.4,-1.7) 162(4.4,1.7) 163(5.2,-1.7) 164(5.2,1.7) 165(6,-1.7) 166(6,1.7) 167(6.8,-1.7) 168(6.8,1.7) 169(7.6,-1.7) 170(7.6,1.7) 171(8.4,-1.7) 172(8.4,1.7) 173(9.2,-1.7) 174(9.2,1.7) 175(10,-1.7) 176(10,1.7) 177(10.8,-1.7) 178(10.8,1.7) 179(11.6,-1.7) 180(11.6,1.7)
  silkscreen extent -14.68,-3.88 14.68,3.88, body extent -14.3,-3.5 14.3,3.5, height 7.95
D0008A_N [mm] "SOIC, 8-Leads, Body 4.9x3.9mm, Pitch 1.27mm, IPC Medium Density"
  oval 1.45x0.6 smd: 1(-2.725,1.905) 2(-2.725,0.635) 3(-2.725,-0.635) 4(-2.725,-1.905) 5(2.725,-1.905) 6(2.725,-0.635) 7(2.725,0.635) 8(2.725,1.905)
  silkscreen extent -3.3,-2.5 0.9,2.5, body extent -3,-2.45 3,2.45, height 1.63
D0014A_N [mm] "SOIC, 14-Leads, Body 8.7x3.9mm, Pitch 1.27mm, IPC Medium Density"
  oval 1.45x0.6 smd: 1(-2.725,3.81) 2(-2.725,2.54) 3(-2.725,1.27) 4(-2.725,0) 5(-2.725,-1.27) 6(-2.725,-2.54) 7(-2.725,-3.81) 8(2.725,-3.81) 9(2.725,-2.54) 10(2.725,-1.27) 11(2.725,0) 12(2.725,1.27) 13(2.725,2.54) 14(2.725,3.81)
  silkscreen extent -3.3,-4.4 0.9,4.4, body extent -3.02,-4.32 3.02,4.32, height 1.6
DQH0008A#1 [mm] "TI"
  rrect39% 0.91x0.51 smd paste-0.05 mask-0.05: 1(-2.795,1.905) 2(-2.795,0.635) 3(-2.795,-0.635) 4(-2.795,-1.905) 5(2.795,-1.905) 6(2.795,-0.635) 7(2.795,0.635) 8(2.795,1.905)
  rrect9% 1.14x1.23 on Top Paste: 9(-1.06,-1.43) 9(-1.06,0) 9(-1.06,1.43) 9(0.28,-1.43) 9(0.28,0) 9(0.28,1.43) 9(1.62,-1.43) 9(1.62,0) 9(1.62,1.43)
  rrect2% 4.02x4.42 on Top Solder: 9(0.38,0)
  rrect2% 4.93x4.52 smd paste-3 mask-3: 9(0.786,0)
  silkscreen extent -3.17,-2.68 3.18,2.68, body extent -3.05,-2.55 3.05,2.55, height 1.06
DQH0008A#2 [mm] "TI"
  rrect39% 0.91x0.51 smd paste-0.05 mask-0.05: 1(-2.795,1.905) 2(-2.795,0.635) 3(-2.795,-0.635) 4(-2.795,-1.905) 5(2.795,-1.905) 6(2.795,-0.635) 7(2.795,0.635) 8(2.795,1.905)
  rrect9% 1.14x1.23 on Bottom Paste: 9(-1.06,-1.43) 9(-1.06,0) 9(-1.06,1.43) 9(0.28,-1.43) 9(0.28,0) 9(0.28,1.43) 9(1.62,-1.43) 9(1.62,0) 9(1.62,1.43)
  rrect2% 4.02x4.42 on Bottom Solder: 9(0.38,0)
  rrect2% 4.93x4.52 smd paste-3 mask-3: 9(0.786,0)
  silkscreen extent -3.18,-2.68 3.17,2.68, body extent -3.05,-2.55 3.05,2.55, height 1.06
DQY0008A [mm] "LSON-CLIP-8"
  rrect24% 0.81x0.41 smd mask+0: 1(-2.795,1.905) 2(-2.795,0.635)
  rrect24% 0.81x0.41 smd: 3(-2.795,-0.635) 4(-2.795,-1.905) 5(2.795,-1.905) 6(2.795,-0.635) 8(2.795,1.905)
  rrect24% 0.81x0.41 smd mask+0.102: 7(2.795,0.635)
  rrect3% 3.156x4.319 smd paste-2.217: 9(0,0)
  Top Layer region: -3.25,0.48 -3.25,2.06 -3.237,2.11 -3.2,2.147 -3.15,2.16 -3.15,2.16 -2.44,2.16 -2.402,2.152 -2.369,2.131 -2.348,2.098 -2.34,2.06 -2.34,2.06 -2.34,0.48 -2.348,0.442 -2.369,0.409 -2.402,0.388 -2.44,0.38 -2.44,0.38 -3.15,0.38 -3.188,0.388 -3.221,0.409 -3.242,0.442 -3.25,0.48
  silkscreen extent -3,-2.65 3,2.65, body extent -3,-2.5 3,2.5, height 1.6
DRV0006A-MFG [mm]
  rrect33% 0.45x0.3 smd paste+0 mask+0: 1(-0.975,0.65) 2(-0.975,0) 3(-0.975,-0.65) 4(0.975,-0.65) 5(0.975,0) 6(0.975,0.65)
  rrect10% 1x1.6 smd paste-1000 mask+0: 7(0,0)
  silkscreen extent -1.87,-1.17 1.05,1.17, body extent -1,-1 1,1, height 0.8
FCC_disclaimer [mil]
Fischer_SL-11-112-03G [mm] "TH, 3-Leads, Body 2.5x7.62mm, Pitch 2.54mm"
  rect 1.4x1.4 hole 0.9: 1(-2.54,0)
  round 1.4 hole 0.9: 2(0,0) 3(2.54,0)
  silkscreen extent -4.58,-1.25 3.81,1.25, body extent -3.81,-1.25 3.81,1.25, height 8.4
FP-GRM155C81E105KE11D_0402-MFG [mm]
  rrect25% 0.4x0.5 smd paste+0 mask+0: 1(-0.4,0) 2(0.4,0)
  body extent -0.7,-0.4 0.7,0.4, height 0.25
FP-PA4059.550HLT_SMT_IND_5MM5_5MM7-MFG [mm]
  rrect5% 2x2.5 smd paste+0 mask+0: 1(-1.9,0) 2(1.9,0)
  silkscreen extent -2.75,-2.85 2.75,2.85, body extent -3,-2.95 3,2.95, height 0.25
FP-TCN4227M025R0100_2924-MFG [mm]
  rrect3% 3.4x4.75 smd paste+0 mask+0: 1(2.15,0)
  rrect5% 2.2x4.75 smd paste+0 mask+0: 2(-2.75,0)
  silkscreen extent -4.75,-3.15 3.75,3.15, body extent -3.95,-3.25 3.95,3.25, height 0.25
FP-XEL3530-501MEC_SMT_IND_3MM2_3MM5-MFG [mm]
  rrect12% 0.81x3.2 smd paste+0 mask+0: 1(-0.9,0) 2(0.9,0)
  body extent -1.78,-1.92 1.78,1.92, height 0.25
GX_2TERM [mm] "PANASONIC"
  rect 2.8x2.4 smd: 1(-3.4,0) 2(3.4,0)
  silkscreen extent -4.45,-2.4 3.8,2.4, body extent -3.75,-2.25 3.75,2.25, height 2.01
Johnson_131-3711-201 [mil] "Connector, SMT, SMB Jack Assembly"
  round 68 smd: 1(0,0)
  round 30 smd: 2(-100,100) 3(100,100) 4(100,-100) 5(-100,-100)
  Top Layer region: -47.5,-140 -47.5,-65 -47.5,-64.99 -71.78,-36.45 -80.5,0 -71.78,36.45 -47.5,64.99 -47.5,64.99 -47.5,65 -47.5,140 -140.5,140 -140.5,-140
  Top Layer region: 47.5,-140 47.5,-65 47.5,-64.99 71.78,-36.45 80.5,0 71.78,36.45 47.5,64.99 47.5,64.99 47.5,65 47.5,140 140.5,140 140.5,-140
  silkscreen extent -152,-152 152,152, body extent -126,-126 127,127, height 328
Keystone5000#1 [mil] "For Keystone 500x miniature loop terminals"
  round 80 hole 40: 1(0,0)
  silkscreen extent -52,-52 52,52, body extent -49,-49 49,49, height 182
Keystone5000#2 [mil] "For Keystone 500x miniature loop terminals"
  round 80 hole 40: 1(0,1.22)
  silkscreen extent -52,-52 52,52, body extent -49,-49 49,49, height 182
Keystone5001 [mil] "For Keystone 500x miniature loop terminals"
  round 80 hole 40: 1(0,0)
  silkscreen extent -52,-52 52,52, body extent -49,-49 49,49, height 182
Keystone5005 [mil] "Keystone Compact loops"
  round 87 hole 63: 1(0,0)
  silkscreen extent -70,-70 70,70, body extent -63,-63 62,63, height 225
Keystone5006 [mil] "Keystone Compact loops"
  round 87 hole 63: 1(0,0)
  silkscreen extent -70,-70 70,70, body extent -63,-63 62,63, height 225
Keystone5007 [mil] "Keystone Compact loops"
  round 87 hole 63: 1(0,0)
  silkscreen extent -70,-70 70,70, body extent -63,-63 62,63, height 225
Keystone_1902C [mil] "Hex Standoff, 4-40 threaded, nylon"
  round 1 on Mech4: 0(0,0)
  body extent -145,-126 146,126, height 501
LED_LTST-C170_Red [mm] "LITE-ON"
  rect 1.2x1.2 smd: 1(-1.05,0) 2(1.05,0)
  silkscreen extent -1.6,-1 2.2,1, body extent -1.05,-0.67 1.05,0.67, height 1.1
LTST-C170KGKT_Green [mm] "LITE-ON"
  rect 1.2x1.2 smd: 1(-1.05,0) 2(1.05,0)
  silkscreen extent -1.6,-1 2.2,1, body extent -1.05,-0.67 1.05,0.67, height 1.1
Molex_52745-0633 [mm] "FFC/FPC Connector, 6 POS, 0.5mm, R/A, SMT"
  rect 0.3x0.8 smd: 1(-1.25,0.75) 2(-0.75,0.75) 3(-0.25,0.75) 4(0.25,0.75) 5(0.75,0.75) 6(1.25,0.75)
  round 1.524 smd: MP1(-3.6,-0.75) MP2(3.6,-0.75)
  Top Layer region: 4.9,-1.85 4.9,0.35 2.5,0.35 2.5,-2.7 3.8,-2.7 3.8,-1.85
  Top Layer region: -4.9,-1.85 -4.9,0.35 -2.5,0.35 -2.5,-2.7 -3.8,-2.7 -3.8,-1.85
  Top Layer keep-out region: 2.5,-1.59 1.7,-1.59 1.7,-0.25 2.5,-0.25
  Top Layer keep-out region: -2.5,-1.59 -1.7,-1.59 -1.7,-0.25 -2.5,-0.25
  silkscreen extent -4.55,-5.55 4.55,0.4, body extent -4.55,-5.55 4.55,0.85, height 2
Molex_0022284043 [mm] "Header, 2.54mm, 4x1, TH"
  rect 1.55x1.55 hole 1.02: 1(-3.81,0)
  round 1.55 hole 1.02: 2(-1.27,0) 3(1.27,0) 4(3.81,0)
  silkscreen extent -5.08,-1.24 5.08,1.5, body extent -5.08,-1.24 5.08,1.24, height 8.4
Net-Tie6milsWide_20milsLong#1 [mil] "6 mils wide by 20 mils long"
  rect 10x6 on Mid3 paste-5 mask-5: 1(-5,0) 2(5,0)
Net-Tie6milsWide_20milsLong#2 [mil] "6 mils wide by 20 mils long"
  rect 10x6 on Mid7 paste-5 mask-5: 1(-5,0) 2(5,0)
Net-Tie_10mil [mil] "10mil net tie, no solder mask opening, no solder paste"
  rect 10x10 smd paste-5 mask-5: 1(-10,0) 2(10,0)
  Top Layer region: -6,5 6,5 6,-5 -6,-5
Net-Tie_10milWide_30milLong [mil] "10mil net tie, no solder mask opening, no solder paste"
  rect 30x10 smd paste-5 mask-5: 1(-15,0) 2(15,0)
"NY PMS 440 0025 PH" [mm] "4-40 nylon screw and mounting hole"
  round 8 hole 3.2: 1(0,0)
  body extent -3.3,-3.3 3.3,3.3, height 2.69
Phoenix_1935776 [mm] "Terminal Block, 2x1, 5mm, TH"
  rect 1.8x1.8 hole 1.3: 1(-2.5,0)
  round 1.8 hole 1.3: 2(2.5,0)
  silkscreen extent -5.3,-4.5 5,4.5, body extent -5,-4.5 5,4.5, height 13.5
RDB0051A-MFG#1 [mm]
  round 0.256 smd paste-1000 mask+0: 1(-2.267,3.563) 15(-2.267,-3.562)
  rrect40% 0.7x0.25 smd paste+0 mask+0: 2(-2.6,3) 3(-2.6,2.5) 7(-2.6,0.5) 8(-2.6,0) 9(-2.6,-0.5) 13(-2.6,-2.5) 14(-2.6,-3) 25(2.6,-3) 26(2.6,-2.5) 30(2.6,-0.5) 31(2.6,0) 32(2.6,0.5) 36(2.6,2.5) 37(2.6,3)
  rrect40% 1.2x0.25 smd paste+0 mask+0: 4(-2.35,2) 5(-2.35,1.5) 6(-2.35,1) 10(-2.35,-1) 11(-2.35,-1.5) 12(-2.35,-2) 27(2.35,-2) 28(2.35,-1.5) 29(2.35,-1) 33(2.35,1) 34(2.35,1.5) 35(2.35,2)
  rrect40% 0.25x0.7 smd paste+0 mask+0: 16(-1.75,-3.85) 17(-1.25,-3.85) 18(-0.75,-3.85) 19(-0.25,-3.85) 20(0.25,-3.85) 21(0.75,-3.85) 22(1.25,-3.85) 23(1.75,-3.85) 39(1.75,3.85) 40(1.25,3.85) 41(0.75,3.85) 42(0.25,3.85) 43(-0.25,3.85) 44(-0.75,3.85) 45(-1.25,3.85) 46(-1.75,3.85)
  round 0.324 smd paste-1000 mask+0: 24(2.312,-3.562) 38(2.312,3.563)
  rrect12% 2.45x0.82 smd paste-1000 mask-1000: 47(0,2.06) 48(0,1.02) 49(0,0) 50(0,-1.02) 51(0,-2.06)
  Top Layer region: -2.955,-3.624 -2.955,-3.425 -2.951,-3.406 -2.94,-3.389 -2.923,-3.379 -2.904,-3.375 -2.904,-3.375 -2.175,-3.375 -2.156,-3.379 -2.139,-3.39 -2.129,-3.407 -2.125,-3.426 -2.125,-3.426 -2.125,-3.825 -2.129,-3.844 -2.14,-3.861 -2.157,-3.871 -2.176,-3.875 -2.176,-3.875 -2.375,-3.875 -2.394,-3.871 -2.411,-3.86 -2.421,-3.843 -2.425,-3.824 -2.425,-3.824 -2.425,-3.726 -2.429,-3.707 -2.439,-3.69 -2.456,-3.679 -2.475,-3.675 -2.475,-3.675 -2.9,-3.675 -2.921,-3.673 -2.939,-3.662 -2.951,-3.645 -2.955,-3.624
  Top Layer region: 2.955,-3.624 2.955,-3.425 2.951,-3.406 2.94,-3.389 2.923,-3.379 2.904,-3.375 2.904,-3.375 2.175,-3.375 2.156,-3.379 2.139,-3.39 2.129,-3.407 2.125,-3.426 2.125,-3.426 2.125,-3.825 2.129,-3.844 2.14,-3.861 2.157,-3.871 2.176,-3.875 2.176,-3.875 2.375,-3.875 2.394,-3.871 2.411,-3.86 2.421,-3.843 2.425,-3.824 2.425,-3.824 2.425,-3.726 2.429,-3.707 2.439,-3.69 2.456,-3.679 2.475,-3.675 2.475,-3.675 2.9,-3.675 2.921,-3.673 2.939,-3.662 2.951,-3.645 2.955,-3.624
  Top Layer region: 2.955,3.624 2.955,3.425 2.951,3.406 2.94,3.389 2.923,3.379 2.904,3.375 2.904,3.375 2.175,3.375 2.156,3.379 2.139,3.39 2.129,3.407 2.125,3.426 2.125,3.426 2.125,3.825 2.129,3.844 2.14,3.861 2.157,3.871 2.176,3.875 2.176,3.875 2.375,3.875 2.394,3.871 2.411,3.86 2.421,3.843 2.425,3.824 2.425,3.824 2.425,3.726 2.429,3.707 2.439,3.69 2.456,3.679 2.475,3.675 2.475,3.675 2.9,3.675 2.921,3.673 2.939,3.662 2.951,3.645 2.955,3.624
  Top Layer region: -2.955,3.624 -2.955,3.425 -2.951,3.406 -2.94,3.389 -2.923,3.379 -2.904,3.375 -2.904,3.375 -2.175,3.375 -2.156,3.379 -2.139,3.39 -2.129,3.407 -2.125,3.426 -2.125,3.426 -2.125,3.825 -2.129,3.844 -2.14,3.861 -2.157,3.871 -2.176,3.875 -2.176,3.875 -2.375,3.875 -2.394,3.871 -2.411,3.86 -2.421,3.843 -2.425,3.824 -2.425,3.824 -2.425,3.726 -2.429,3.707 -2.439,3.69 -2.456,3.679 -2.475,3.675 -2.475,3.675 -2.9,3.675 -2.921,3.673 -2.939,3.662 -2.951,3.645 -2.955,3.624
  Top Layer region: -1.25,2.45 -1.243,2.475 -1.225,2.493 -1.2,2.5 -1.2,2.5 1.2,2.5 1.225,2.493 1.243,2.475 1.25,2.45 1.25,2.45 1.25,-2.45 1.243,-2.475 1.225,-2.493 1.2,-2.5 1.2,-2.5 -1.2,-2.5 -1.225,-2.493 -1.243,-2.475 -1.25,-2.45 -1.25,-2.45
  silkscreen extent -3.65,-4.3 2.8,4.3, body extent -3.06,-4.3 3.06,4.3, height 0.25
RDB0051A-MFG#2 [mm]
  round 0.256 smd paste-1000 mask+0: 1(-2.267,3.562) 15(-2.267,-3.562)
  rrect40% 0.7x0.25 smd paste+0 mask+0: 2(-2.6,3) 3(-2.6,2.5) 7(-2.6,0.5) 8(-2.6,0) 9(-2.6,-0.5) 13(-2.6,-2.5) 14(-2.6,-3) 25(2.6,-3) 26(2.6,-2.5) 30(2.6,-0.5) 31(2.6,0) 32(2.6,0.5) 36(2.6,2.5) 37(2.6,3)
  rrect40% 1.2x0.25 smd paste+0 mask+0: 4(-2.35,2) 5(-2.35,1.5) 6(-2.35,1) 10(-2.35,-1) 11(-2.35,-1.5) 12(-2.35,-2) 27(2.35,-2) 28(2.35,-1.5) 29(2.35,-1) 33(2.35,1) 34(2.35,1.5) 35(2.35,2)
  rrect40% 0.25x0.7 smd paste+0 mask+0: 16(-1.75,-3.85) 17(-1.25,-3.85) 18(-0.75,-3.85) 19(-0.25,-3.85) 20(0.25,-3.85) 21(0.75,-3.85) 22(1.25,-3.85) 23(1.75,-3.85) 39(1.75,3.85) 40(1.25,3.85) 41(0.75,3.85) 42(0.25,3.85) 43(-0.25,3.85) 44(-0.75,3.85) 45(-1.25,3.85) 46(-1.75,3.85)
  round 0.324 smd paste-1000 mask+0: 24(2.312,-3.562) 38(2.312,3.562)
  rrect4% 2.5x5 smd paste-1000 mask+0: 47-48-49-50-51(0,0)
  Top Layer region: -2.955,-3.624 -2.955,-3.425 -2.951,-3.406 -2.94,-3.389 -2.923,-3.379 -2.904,-3.375 -2.904,-3.375 -2.175,-3.375 -2.156,-3.379 -2.139,-3.39 -2.129,-3.407 -2.125,-3.426 -2.125,-3.426 -2.125,-3.825 -2.129,-3.844 -2.14,-3.861 -2.157,-3.871 -2.176,-3.875 -2.176,-3.875 -2.375,-3.875 -2.394,-3.871 -2.411,-3.86 -2.421,-3.843 -2.425,-3.824 -2.425,-3.824 -2.425,-3.726 -2.429,-3.707 -2.439,-3.69 -2.456,-3.679 -2.475,-3.675 -2.475,-3.675 -2.9,-3.675 -2.921,-3.673 -2.939,-3.662 -2.951,-3.645 -2.955,-3.624
  Top Layer region: -2.955,3.624 -2.955,3.425 -2.951,3.406 -2.94,3.389 -2.923,3.379 -2.904,3.375 -2.904,3.375 -2.175,3.375 -2.156,3.379 -2.139,3.39 -2.129,3.407 -2.125,3.426 -2.125,3.426 -2.125,3.825 -2.129,3.844 -2.14,3.861 -2.157,3.871 -2.176,3.875 -2.176,3.875 -2.375,3.875 -2.394,3.871 -2.411,3.86 -2.421,3.843 -2.425,3.824 -2.425,3.824 -2.425,3.726 -2.429,3.707 -2.439,3.69 -2.456,3.679 -2.475,3.675 -2.475,3.675 -2.9,3.675 -2.921,3.673 -2.939,3.662 -2.951,3.645 -2.955,3.624
  Top Layer region: 2.955,-3.624 2.955,-3.425 2.951,-3.406 2.94,-3.389 2.923,-3.379 2.904,-3.375 2.904,-3.375 2.175,-3.375 2.156,-3.379 2.139,-3.39 2.129,-3.407 2.125,-3.426 2.125,-3.426 2.125,-3.825 2.129,-3.844 2.14,-3.861 2.157,-3.871 2.176,-3.875 2.176,-3.875 2.375,-3.875 2.394,-3.871 2.411,-3.86 2.421,-3.843 2.425,-3.824 2.425,-3.824 2.425,-3.726 2.429,-3.707 2.439,-3.69 2.456,-3.679 2.475,-3.675 2.475,-3.675 2.9,-3.675 2.921,-3.673 2.939,-3.662 2.951,-3.645 2.955,-3.624
  Top Layer region: 2.955,3.624 2.955,3.425 2.951,3.406 2.94,3.389 2.923,3.379 2.904,3.375 2.904,3.375 2.175,3.375 2.156,3.379 2.139,3.39 2.129,3.407 2.125,3.426 2.125,3.426 2.125,3.825 2.129,3.844 2.14,3.861 2.157,3.871 2.176,3.875 2.176,3.875 2.375,3.875 2.394,3.871 2.411,3.86 2.421,3.843 2.425,3.824 2.425,3.824 2.425,3.726 2.429,3.707 2.439,3.69 2.456,3.679 2.475,3.675 2.475,3.675 2.9,3.675 2.921,3.673 2.939,3.662 2.951,3.645 2.955,3.624
  silkscreen extent -3.65,-4.3 2.8,4.3, body extent -3.06,-4.3 3.06,4.3, height 0.25
RL1632L4 [mm] "SMD, 2-Leads, Body 1.5x3.15mm"
  rect 1x2.32 smd: 1(-0.875,-0.59) 2(0.875,-0.59)
  rect 1x0.8 smd: 3(-0.875,1.35) 4(0.875,1.35)
  body extent -0.87,-1.7 0.87,1.7, height 1.13
RSB0040E [mm] "QFN, 40-Leads, Body 5x5mm, Pitch 0.4mm, Thermal Pad 3.15x3.15mm, TI Recommended"
  rrect50% 0.6x0.2 smd: 1(-2.4,1.8) 2(-2.4,1.4) 3(-2.4,1) 4(-2.4,0.6) 5(-2.4,0.2) 6(-2.4,-0.2) 7(-2.4,-0.6) 8(-2.4,-1) 9(-2.4,-1.4) 10(-2.4,-1.8) 21(2.4,-1.8) 22(2.4,-1.4) 23(2.4,-1) 24(2.4,-0.6) 25(2.4,-0.2) 26(2.4,0.2) 27(2.4,0.6) 28(2.4,1) 29(2.4,1.4) 30(2.4,1.8)
  rrect50% 0.2x0.6 smd: 11(-1.8,-2.4) 12(-1.4,-2.4) 13(-1,-2.4) 14(-0.6,-2.4) 15(-0.2,-2.4) 16(0.2,-2.4) 17(0.6,-2.4) 18(1,-2.4) 19(1.4,-2.4) 20(1.8,-2.4) 31(1.8,2.4) 32(1.4,2.4) 33(1,2.4) 34(0.6,2.4) 35(0.2,2.4) 36(-0.2,2.4) 37(-0.6,2.4) 38(-1,2.4) 39(-1.4,2.4) 40(-1.8,2.4)
  rrect7% 1.37x1.37 on Top Paste: 41(-0.785,0.785) 41(-0.785,-0.785) 41(0.785,0.785) 41(0.785,-0.785)
  rrect3% 3.15x3.15 smd paste-1.575: 41(0,0)
  silkscreen extent -2.7,-2.7 2.7,2.7, body extent -2.55,-2.55 2.55,2.55, height 0.81
RSK0064C [mm] "QFN, 64-Leads, Body 8x8mm, Pitch 0.4mm"
  oval 0.7x0.2 smd: 1(-3.85,3) 2(-3.85,2.6) 3(-3.85,2.2) 4(-3.85,1.8) 5(-3.85,1.4) 6(-3.85,1) 7(-3.85,0.6) 8(-3.85,0.2) 9(-3.85,-0.2) 10(-3.85,-0.6) 11(-3.85,-1) 12(-3.85,-1.4) 13(-3.85,-1.8) 14(-3.85,-2.2) 15(-3.85,-2.6) 16(-3.85,-3) 33(3.85,-3) 34(3.85,-2.6) 35(3.85,-2.2) 36(3.85,-1.8) 37(3.85,-1.4) 38(3.85,-1) 39(3.85,-0.6) 40(3.85,-0.2) 41(3.85,0.2) 42(3.85,0.6) 43(3.85,1) 44(3.85,1.4) 45(3.85,1.8) 46(3.85,2.2) 47(3.85,2.6) 48(3.85,3)
  oval 0.2x0.7 smd: 17(-3,-3.85) 18(-2.6,-3.85) 19(-2.2,-3.85) 20(-1.8,-3.85) 21(-1.4,-3.85) 22(-1,-3.85) 23(-0.6,-3.85) 24(-0.2,-3.85) 25(0.2,-3.85) 26(0.6,-3.85) 27(1,-3.85) 28(1.4,-3.85) 29(1.8,-3.85) 30(2.2,-3.85) 31(2.6,-3.85) 32(3,-3.85) 49(3,3.85) 50(2.6,3.85) 51(2.2,3.85) 52(1.8,3.85) 53(1.4,3.85) 54(1,3.85) 55(0.6,3.85) 56(0.2,3.85) 57(-0.2,3.85) 58(-0.6,3.85) 59(-1,3.85) 60(-1.4,3.85) 61(-1.8,3.85) 62(-2.2,3.85) 63(-2.6,3.85) 64(-3,3.85)
  rect 5.7x5.7 smd paste-5.7: 65(0,0)
  silkscreen extent -4.18,-4.18 4.17,4.17, body extent -4.08,-4.08 4.08,4.08, height 1.01
RWJ0041A [mm] "QFN, 41-Leads, Body 5x6mm, Pitch 0.45mm"
  rrect57% 0.7x0.35 smd paste-0.05 mask-0.05: 1(-2.4,2.275) 2(-2.4,1.825) 3(-2.4,1.375) 4(-2.4,0.925) 5(-2.4,0.475) 6(-2.4,0.025)
  rrect40% 0.6x0.25 smd mask+0: 7(-2.4,-1.05) 8(-2.4,-1.5) 9(-2.4,-1.95) 20(2.4,-2.05) 21(2.4,-1.6) 22(2.4,-1.15) 23(2.4,-0.7) 24(2.4,-0.25) 25(2.4,0.375) 26(2.4,0.825) 27(2.4,1.275) 28(2.4,1.725) 29(2.4,2.175)
  rrect100% 0.2x0.4 smd paste-0.4 mask-0.4: 10(-2.025,-2.85) 11(-1.575,-2.85) 12(-1.125,-2.85) 13(-0.675,-2.85) 14(-0.225,-2.85) 15(0.225,-2.85) 16(0.675,-2.85) 17(1.125,-2.85) 18(1.575,-2.85) 19(2.025,-2.85)
  rrect12% 0.8x1.33 on Top Paste: 24(-1.5,-1.505)
  rrect12% 0.8x0.92 on Top Paste: 24(-0.5,-1.71) 24(-0.5,-0.59) 24(0.5,-1.71) 24(0.5,-0.59) 24(1.5,-1.71) 24(1.5,-0.59)
  rrect57% 0.35x0.7 smd paste-0.05 mask-0.05: 30(2.05,2.9) 31(1.6,2.9) 32(1.15,2.9) 33(0.7,2.9) 34(0.25,2.9) 35(-0.2,2.9) 36(-0.65,2.9) 37(-1.1,2.9) 38(-1.55,2.9) 39(-2,2.9)
  rrect14% 0.69x0.87 on Top Paste: 40(-1.32,0.74) 40(-1.32,1.81) 40(-0.43,0.74) 40(-0.43,1.81)
  rrect11% 1.85x2.05 smd paste-2.05 mask-0.05: 40(-0.875,1.275)
  rrect16% 0.63x0.87 on Top Paste: 40(0.735,0.74) 40(0.735,1.81) 40(1.575,0.74) 40(1.575,1.81)
  rrect50% 0.55x0.4 smd paste-0.05 mask-0.05: 41(-1.525,-0.25)
  Top Layer region: -2.2,-3.2 -2.196,-3.219 -2.185,-3.235 -2.169,-3.246 -2.15,-3.25 -2.15,-3.25 2.15,-3.25 2.169,-3.246 2.185,-3.235 2.196,-3.219 2.2,-3.2 2.2,-3.2 2.2,-2.6 2.196,-2.581 2.185,-2.565 2.169,-2.554 2.15,-2.55 2.15,-2.55 -2.15,-2.55 -2.169,-2.554 -2.185,-2.565 -2.196,-2.581 -2.2,-2.6 -2.2,-2.6
  Top Layer region: 0.35,0.3 0.358,0.262 0.379,0.229 0.412,0.208 0.45,0.2 0.45,0.2 2.65,0.2 2.688,0.208 2.721,0.229 2.742,0.262 2.75,0.3 2.75,0.3 2.75,2.25 2.742,2.288 2.721,2.321 2.688,2.342 2.65,2.35 2.65,2.35 0.45,2.35 0.412,2.342 0.379,2.321 0.358,2.288 0.35,2.25 0.35,2.25
  Top Layer region: -2.75,-2.15 -2.75,-0.85 -2.742,-0.812 -2.721,-0.779 -2.688,-0.758 -2.65,-0.75 -2.65,-0.75 -1,-0.75 -0.981,-0.746 -0.965,-0.735 -0.954,-0.719 -0.95,-0.7 -0.95,-0.7 -0.95,-0.15 -0.942,-0.112 -0.921,-0.079 -0.888,-0.058 -0.85,-0.05 -0.85,-0.05 2.65,-0.05 2.688,-0.058 2.721,-0.079 2.742,-0.112 2.75,-0.15 2.75,-0.15 2.75,-2.15 2.742,-2.188 2.721,-2.221 2.688,-2.242 2.65,-2.25 2.65,-2.25 -2.65,-2.25 -2.688,-2.242 -2.721,-2.221 -2.742,-2.188 -2.75,-2.15
  silkscreen extent -2.65,-3.15 2.65,3.15, body extent -2.5,-3 2.5,3, height 1.04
